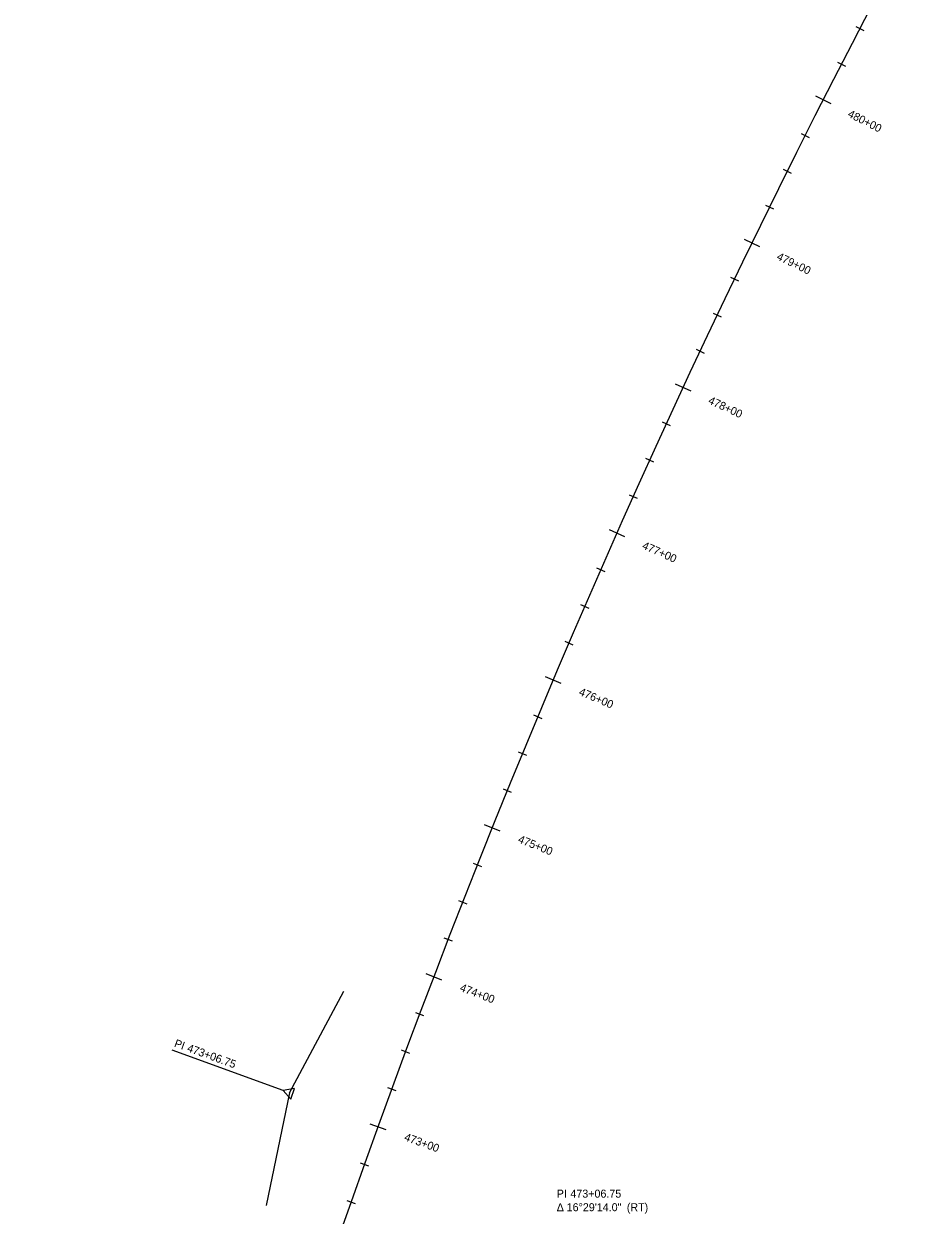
# Model space of a CAD drawing. Extents: x 2300830 to 2307917, y 756066 to 766359.
# Drawn here: x 2300916 to 2301469, y 756817 to 757561 of the extents above; entities that cross this region are included whole.
import ezdxf

# ---------------------------------------------------------------- set-up
doc = ezdxf.new("R2010")
doc.units = 0
for name, color, linetype in [('Draft_Curve Data Label', 7, 'Continuous'), ('Draft_Station Cardinal Lines', 7, 'Continuous'), ('Draft_Station Cardinal Points', 7, 'Continuous'), ('Draft_Station Labels Major', 7, 'Continuous'), ('Draft_Station Ticks Major', 7, 'Continuous'), ('Draft_Station Ticks Minor', 7, 'Continuous'), ('Geom_Baseline', 7, 'Continuous')]:
    doc.layers.add(name, color=color, linetype=linetype)

msp = doc.modelspace()

# ---------------------------------------------------------------- linework, layer by layer
at = {"layer": 'Draft_Station Cardinal Lines'}
for p, q in [((2301081.64, 756893.08), (2301115.62, 756956.56)), ((2301077.69, 756894.51), (2301008.31, 756919.66)), ((2301081.64, 756893.08), (2301067.07, 756822.57))]:
    msp.add_line(p, q, dxfattribs=at)
msp.add_lwpolyline([(2301077.73, 756894.5), (2301082.37, 756888.99), (2301084.82, 756895.76)], close=True, dxfattribs=at)
at = {"layer": 'Draft_Station Cardinal Points'}
for p, q in [((2301008.31, 756919.66), (2301008.31, 756919.66)), ((2301081.64, 756893.08), (2301081.64, 756893.08))]:
    msp.add_line(p, q, dxfattribs=at)
at = {"layer": 'Draft_Station Ticks Major'}
for p, q in [((2301410.5, 757516.11), (2301419.96, 757511.29)), ((2301365.86, 757426.53), (2301375.41, 757421.87)), ((2301322.82, 757336.16), (2301332.44, 757331.68)), ((2301281.37, 757245.05), (2301291.07, 757240.74)), ((2301241.54, 757153.23), (2301251.32, 757149.09)), ((2301203.33, 757060.71), (2301213.19, 757056.75)), ((2301166.77, 756967.54), (2301176.69, 756963.74)), ((2301131.85, 756873.73), (2301141.84, 756870.11))]:
    msp.add_line(p, q, dxfattribs=at)
at = {"layer": 'Draft_Station Ticks Minor'}
for p, q in [((2301435.7, 757559.42), (2301440.59, 757556.87)), ((2301424.2, 757537.21), (2301429.11, 757534.68)), ((2301401.5, 757492.63), (2301406.43, 757490.15)), ((2301390.29, 757470.27), (2301395.23, 757467.81)), ((2301379.19, 757447.86), (2301384.14, 757445.42)), ((2301357.28, 757402.89), (2301362.25, 757400.49)), ((2301346.47, 757380.33), (2301351.45, 757377.95)), ((2301335.76, 757357.72), (2301340.76, 757355.37)), ((2301314.65, 757312.38), (2301319.66, 757310.07)), ((2301304.24, 757289.63), (2301309.26, 757287.35)), ((2301293.93, 757266.84), (2301298.97, 757264.58)), ((2301273.62, 757221.13), (2301278.68, 757218.91)), ((2301263.62, 757198.2), (2301268.68, 757196)), ((2301253.72, 757175.23), (2301258.79, 757173.06)), ((2301234.21, 757129.17), (2301239.31, 757127.04)), ((2301224.62, 757106.07), (2301229.72, 757103.96)), ((2301215.12, 757082.93), (2301220.23, 757080.85)), ((2301196.44, 757036.53), (2301201.57, 757034.49)), ((2301187.25, 757013.26), (2301192.39, 757011.25)), ((2301178.16, 756989.96), (2301183.31, 756987.97)), ((2301160.3, 756943.23), (2301165.46, 756941.28)), ((2301151.52, 756919.81), (2301156.7, 756917.89)), ((2301142.85, 756896.35), (2301148.03, 756894.45)), ((2301125.81, 756849.32), (2301131.01, 756847.46)), ((2301117.45, 756825.74), (2301122.66, 756823.91))]:
    msp.add_line(p, q, dxfattribs=at)
at = {"layer": 'Geom_Baseline'}
msp.add_arc((2306463.05, 754942.84), 5664.75, 151.8357, 168.32293, dxfattribs=at)

# ---------------------------------------------------------------- texts
at = {"layer": 'Draft_Curve Data Label'}
for s, p in [('PI ', (2301248.68, 756827.54)), ('473+06.75', (2301257.22, 756827.54)), ('Δ ', (2301248.68, 756819.04)), ('16°29\'14.0"', (2301254.9, 756819.04)), (' (RT)', (2301290.63, 756819.04))]:
    msp.add_text(s, height=5, dxfattribs=at).set_placement(p)
at = {"layer": 'Draft_Station Cardinal Points'}
for s, p in [('PI ', (2301009.15, 756921.99)), ('473+06.75', (2301017.18, 756919.08))]:
    msp.add_text(s, height=5, rotation=340.07931, dxfattribs=at).set_placement(p)
at = {"layer": 'Draft_Station Labels Major'}
for s, rotation, p in [('480+00', 333.01015, (2301430.16, 757503.29)), ('479+00', 334.02159, (2301385.75, 757414.05)), ('478+00', 335.03303, (2301342.92, 757324.04)), ('477+00', 336.04448, (2301301.68, 757233.29)), ('476+00', 337.05592, (2301262.06, 757141.83)), ('475+00', 338.06736, (2301224.05, 757049.68)), ('474+00', 339.07881, (2301187.68, 756956.87)), ('473+00', 340.09025, (2301152.95, 756863.43))]:
    msp.add_text(s, height=5, rotation=rotation, dxfattribs=at).set_placement(p)

doc.saveas('drawing.dxf')
